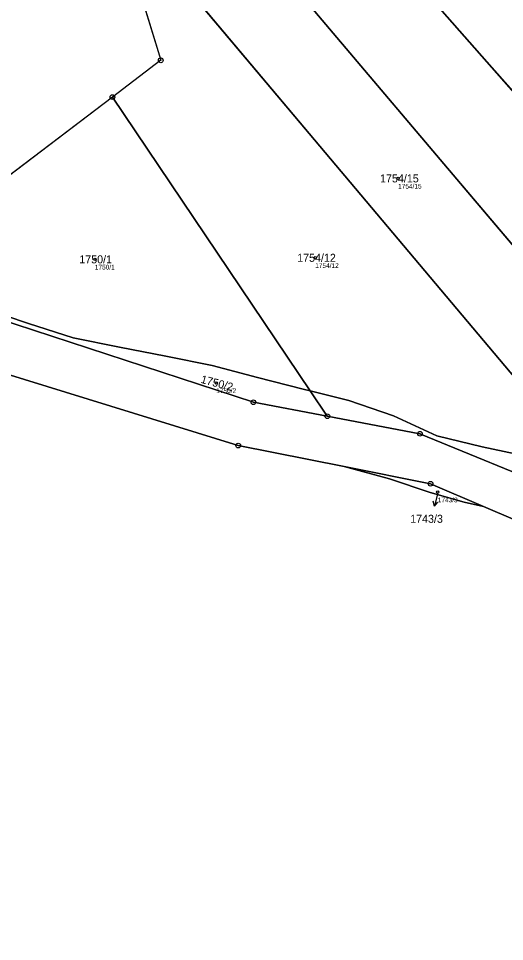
# Model space of a CAD drawing. Extents: x -751550 to -746116, y -1055108 to -1050700.
# Drawn here: x -750591.1 to -750487.8, y -1054406.1 to -1054210.1 of the extents above; entities that cross this region are included whole.
import ezdxf

# ---------------------------------------------------------------- set-up
doc = ezdxf.new("R2010")
doc.units = 0
for name, color, linetype in [('Definiční body', 7, 'Continuous'), ('Hranice parcel', 7, 'Continuous'), ('Parcelní čísla', 7, 'Continuous'), ('Polygon ku', 7, 'Continuous'), ('Polygon parcely', 7, 'Continuous'), ('Pop  PČ popisy', 7, 'Continuous'), ('Značky bodu BP', 7, 'Continuous')]:
    doc.layers.add(name, color=color, linetype=linetype)

msp = doc.modelspace()

# ---------------------------------------------------------------- linework, layer by layer
at = {"layer": 'Definiční body'}
for centre in [(-750510.44, -1054244.03), (-750574.87, -1054261.22), (-750528.05, -1054260.89), (-750549.08, -1054287.45), (-750502.01, -1054310.66)]:
    msp.add_circle(centre, 0.25, dxfattribs=at)
at = {"layer": 'Hranice parcel'}
for p, q in [((-750473.06, -1054301.3), (-750571.28, -1054184.67)), ((-750515.33, -1054192.28), (-750432.52, -1054286.21)), ((-750568.12, -1054195.07), (-750560.86, -1054218.95)), ((-750451.73, -1054298.76), (-750530.91, -1054205.23)), ((-750560.86, -1054218.95), (-750571.15, -1054226.77)), ((-750571.15, -1054226.77), (-750622.01, -1054265.4)), ((-750529.12, -1054289.13), (-750571.15, -1054226.77)), ((-750525.48, -1054294.53), (-750529.12, -1054289.13))]:
    msp.add_line(p, q, dxfattribs=at)
for points in [[(-750492.31, -1054313.68), (-750478.7, -1054319.49), (-750460.39, -1054329.54), (-750446.13, -1054332.7), (-750436.07, -1054329.29), (-750414.64, -1054315.18), (-750394.13, -1054303.69), (-750374.5, -1054301.56), (-750346.87, -1054303.47), (-750308.48, -1054310.33), (-750243.46, -1054301.57), (-750193.86, -1054286.28), (-750177.77, -1054276.34), (-750154.22, -1054242.37)], [(-750622.01, -1054265.4), (-750618.89, -1054266.11), (-750608.2, -1054268.53), (-750598.47, -1054271.66), (-750588.95, -1054274.82), (-750579.46, -1054277.9), (-750569.66, -1054279.87), (-750559.82, -1054281.81), (-750549.98, -1054283.75), (-750540.29, -1054286.31), (-750530.59, -1054288.76), (-750529.12, -1054289.13)], [(-750525.48, -1054294.53), (-750541.19, -1054291.56), (-750599.68, -1054272.45), (-750623.31, -1054266.39)], [(-750603.4, -1054282.55), (-750544.42, -1054300.77), (-750521.88, -1054305.23)], [(-750529.12, -1054289.13), (-750520.89, -1054291.2), (-750511.41, -1054294.43), (-750502.2, -1054298.67), (-750492.56, -1054301.01), (-750483.25, -1054303.05), (-750475.03, -1054304.04), (-750474.1, -1054303.73), (-750473.81, -1054303.43), (-750473.06, -1054301.3)], [(-750475.72, -1054310.57), (-750505.81, -1054298.25), (-750525.48, -1054294.53)], [(-750521.88, -1054305.23), (-750503.56, -1054308.87), (-750492.31, -1054313.68)], [(-750521.88, -1054305.23), (-750512.29, -1054307.87), (-750503.6, -1054310.74), (-750496.39, -1054312.81), (-750492.31, -1054313.68)]]:
    msp.add_lwpolyline(points, dxfattribs=at)
at = {"layer": 'Polygon ku'}
msp.add_lwpolyline([(-750473.66, -1054110.29), (-750486.68, -1054119.14), (-750499.83, -1054128.08), (-750513.17, -1054137.15), (-750533.33, -1054150.85), (-750546.08, -1054157.4), (-750563.73, -1054166.45), (-750575.76, -1054172.63), (-750573.5, -1054178.69), (-750571.28, -1054184.67), (-750568.12, -1054195.07), (-750560.86, -1054218.95), (-750571.15, -1054226.77), (-750622.01, -1054265.4)], dxfattribs=at)
at = {"layer": 'Polygon parcely'}
for points in [[(-750424.93, -1054277.77), (-750407.4, -1054258.24), (-750510.53, -1054140.17), (-750531.08, -1054154.16), (-750543.43, -1054160.4), (-750515.33, -1054192.28), (-750432.52, -1054286.21), (-750432.39, -1054286.11)], [(-750575.76, -1054172.63), (-750573.5, -1054178.69), (-750571.28, -1054184.67), (-750473.06, -1054301.3), (-750470.88, -1054303.76), (-750467.07, -1054298.38), (-750458.46, -1054298.76), (-750453.02, -1054299), (-750451.73, -1054298.76), (-750530.91, -1054205.23), (-750563.73, -1054166.45)], [(-750571.28, -1054184.67), (-750568.12, -1054195.07), (-750560.86, -1054218.95), (-750571.15, -1054226.77), (-750529.12, -1054289.13), (-750520.89, -1054291.2), (-750511.41, -1054294.43), (-750502.2, -1054298.67), (-750492.56, -1054301.01), (-750483.25, -1054303.05), (-750475.03, -1054304.04), (-750474.1, -1054303.73), (-750473.81, -1054303.43), (-750473.06, -1054301.3)], [(-750440.64, -1054292.78), (-750432.52, -1054286.21), (-750515.33, -1054192.28), (-750530.91, -1054205.23), (-750451.73, -1054298.76), (-750446.92, -1054297.86)], [(-750579.46, -1054277.9), (-750569.66, -1054279.87), (-750559.82, -1054281.81), (-750549.98, -1054283.75), (-750540.29, -1054286.31), (-750530.59, -1054288.76), (-750529.12, -1054289.13), (-750571.15, -1054226.77), (-750622.01, -1054265.4), (-750618.89, -1054266.11), (-750608.2, -1054268.53), (-750598.47, -1054271.66), (-750588.95, -1054274.82)], [(-750525.48, -1054294.53), (-750529.12, -1054289.13), (-750530.59, -1054288.76), (-750540.29, -1054286.31), (-750549.98, -1054283.75), (-750559.82, -1054281.81), (-750569.66, -1054279.87), (-750579.46, -1054277.9), (-750588.95, -1054274.82), (-750598.47, -1054271.66), (-750608.2, -1054268.53), (-750618.89, -1054266.11), (-750622.01, -1054265.4), (-750623.31, -1054266.39), (-750599.68, -1054272.45), (-750541.19, -1054291.56)], [(-750475.72, -1054310.57), (-750470.88, -1054303.76), (-750473.06, -1054301.3), (-750473.81, -1054303.43), (-750474.1, -1054303.73), (-750475.03, -1054304.04), (-750483.25, -1054303.05), (-750492.56, -1054301.01), (-750502.2, -1054298.67), (-750511.41, -1054294.43), (-750520.89, -1054291.2), (-750529.12, -1054289.13), (-750525.48, -1054294.53), (-750505.81, -1054298.25)], [(-750521.88, -1054305.23), (-750512.29, -1054307.87), (-750503.6, -1054310.74), (-750496.39, -1054312.81), (-750492.31, -1054313.68), (-750503.56, -1054308.87)]]:
    msp.add_lwpolyline(points, close=True, dxfattribs=at)
for points in [[(-750179.8, -1054262.99), (-750198.44, -1054278.32), (-750245.96, -1054292.88), (-750255.81, -1054294.11), (-750269.26, -1054295.78), (-750308.97, -1054300.71), (-750349.86, -1054293.76), (-750376.14, -1054292.81), (-750401.7, -1054296.95), (-750410.81, -1054302.66), (-750415.47, -1054305.69), (-750436.81, -1054319.23), (-750447.17, -1054322.25), (-750453.92, -1054321.2), (-750461.44, -1054317.06), (-750462.47, -1054316.49), (-750465.99, -1054314.55), (-750470.14, -1054312.85), (-750475.72, -1054310.57), (-750505.81, -1054298.25), (-750525.48, -1054294.53), (-750541.19, -1054291.56), (-750599.68, -1054272.45)], [(-750603.4, -1054282.55), (-750544.42, -1054300.77), (-750521.88, -1054305.23), (-750503.56, -1054308.87), (-750492.31, -1054313.68), (-750478.7, -1054319.49), (-750460.39, -1054329.54), (-750446.13, -1054332.7), (-750436.07, -1054329.29), (-750414.64, -1054315.18), (-750394.13, -1054303.69), (-750374.5, -1054301.56), (-750346.87, -1054303.47), (-750308.48, -1054310.33), (-750243.46, -1054301.57), (-750193.86, -1054286.28), (-750177.77, -1054276.34)], [(-750177.77, -1054276.34), (-750193.86, -1054286.28), (-750243.46, -1054301.57), (-750308.48, -1054310.33), (-750346.87, -1054303.47), (-750374.5, -1054301.56), (-750394.13, -1054303.69), (-750414.64, -1054315.18), (-750436.07, -1054329.29), (-750446.13, -1054332.7), (-750460.39, -1054329.54), (-750478.7, -1054319.49), (-750492.31, -1054313.68), (-750496.39, -1054312.81)], [(-750496.39, -1054312.81), (-750503.6, -1054310.74), (-750512.29, -1054307.87), (-750521.88, -1054305.23), (-750544.42, -1054300.77), (-750603.4, -1054282.55), (-750673.4, -1054331.59), (-750768.53, -1054376.3), (-750783.16, -1054386.95), (-750791.54, -1054396.42), (-750793.14, -1054412.23), (-750799.76, -1054436.79), (-750867.62, -1054438.09), (-750899.78, -1054442.17), (-750944.03, -1054449.07), (-750996.78, -1054461.66), (-750993.45, -1054469.19)]]:
    msp.add_lwpolyline(points, dxfattribs=at)
at = {"layer": 'Pop  PČ popisy'}
for p, q in [((-750502.01, -1054310.74), (-750502.74, -1054313.65)), ((-750502.74, -1054313.65), (-750502.98, -1054312.56)), ((-750502.74, -1054313.65), (-750502.01, -1054312.8))]:
    msp.add_line(p, q, dxfattribs=at)
at = {"layer": 'Značky bodu BP'}
for centre, radius in [((-750560.86, -1054218.95), 0.5), ((-750560.86, -1054218.95), 0.0303), ((-750571.15, -1054226.77), 0.5), ((-750571.15, -1054226.77), 0.0303), ((-750541.19, -1054291.56), 0.5), ((-750541.19, -1054291.56), 0.0303), ((-750525.48, -1054294.53), 0.5), ((-750525.48, -1054294.53), 0.0303), ((-750505.81, -1054298.25), 0.5), ((-750505.81, -1054298.25), 0.0303), ((-750544.42, -1054300.77), 0.5), ((-750544.42, -1054300.77), 0.0303), ((-750503.56, -1054308.87), 0.5), ((-750503.56, -1054308.87), 0.0303)]:
    msp.add_circle(centre, radius, dxfattribs=at)

# ---------------------------------------------------------------- texts
at = {"layer": 'Definiční body'}
for s, p in [('1754/15', (-750510.44, -1054246.19)), ('1750/1', (-750574.87, -1054263.38)), ('1754/12', (-750528.05, -1054263.05)), ('1750/2', (-750549.08, -1054289.61)), ('1743/3', (-750502.01, -1054312.82))]:
    msp.add_text(s, height=1, dxfattribs=at).set_placement(p)
at = {"layer": 'Parcelní čísla'}
for s, p in [('1754/15', (-750514.28, -1054244.88)), ('1750/1', (-750578.18, -1054262.07)), ('1754/12', (-750531.89, -1054261.74)), ('1743/3', (-750507.88, -1054317.17))]:
    msp.add_text(s, height=1.7, dxfattribs=at).set_placement(p)
msp.add_text('1750/2', height=1.7, rotation=345, dxfattribs=at).set_placement((-750552.49, -1054287.42))

doc.saveas('drawing.dxf')
